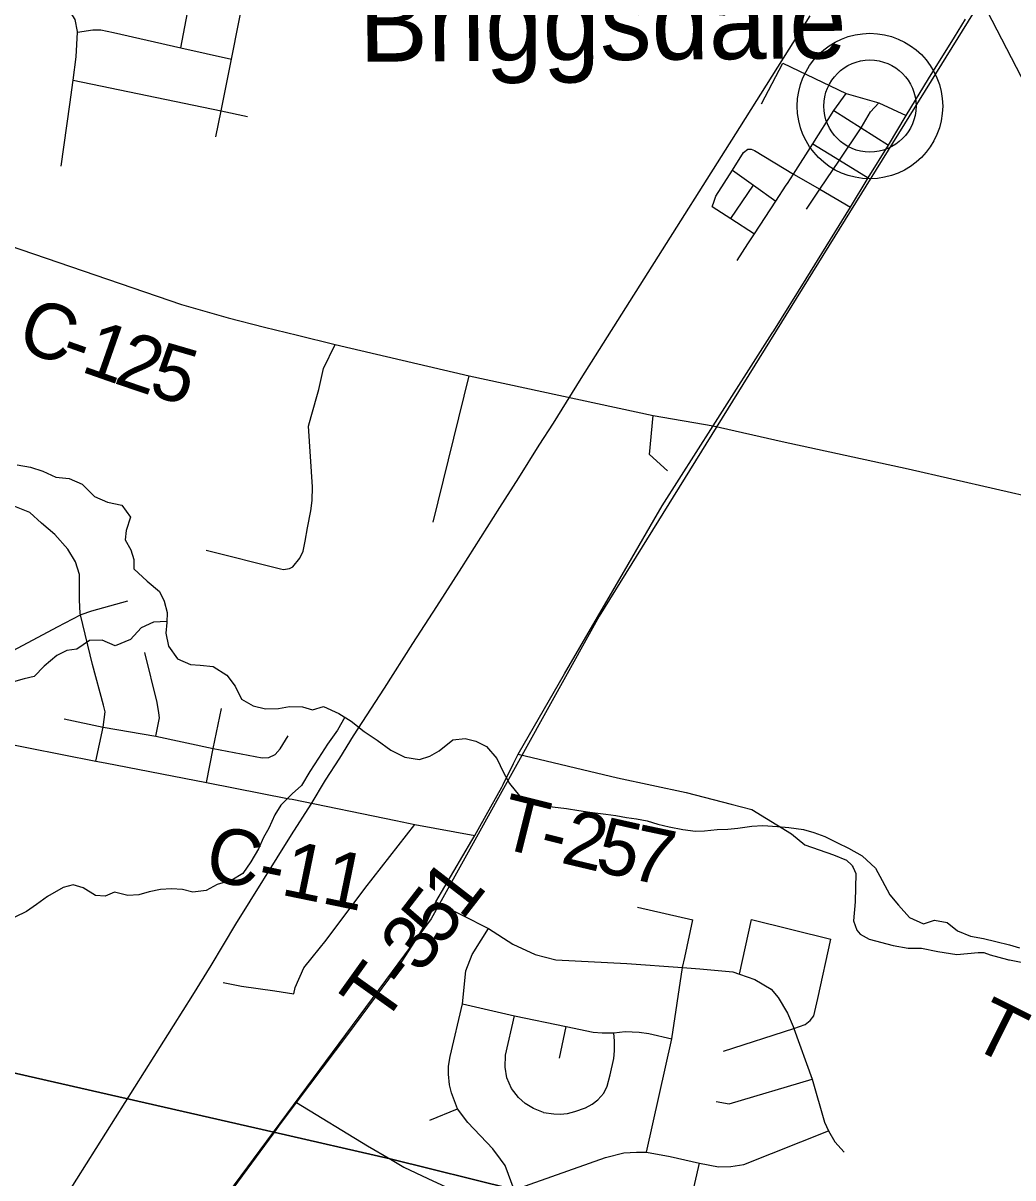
# Model space of a CAD drawing. Extents: x 114604 to 551442, y 316898 to 567001.
# Drawn here: x 185178 to 190526, y 367898 to 374135 of the extents above; entities that cross this region are included whole.
import ezdxf

# ---------------------------------------------------------------- set-up
doc = ezdxf.new("R2010")
doc.units = 0
for name, color, linetype in [('_CIVIL_CONSTRUCTION', 7, 'Continuous'), ('GE_P_Alignment_1000_Bearings', 7, 'Continuous'), ('GE_P_Alignment_1000_Cardinal_Points', 7, 'Continuous'), ('GE_P_Alignment_1000_Stations', 7, 'Continuous'), ('GE_P_Alignment_100_Cardinal_Points', 7, 'Continuous'), ('GE_P_Alignment_500_Bearings', 7, 'Continuous'), ('GE_P_Alignment_500_Distances', 7, 'Continuous'), ('GE_X_Alignment', 7, 'Continuous'), ('PM_P_Cells', 7, 'Continuous'), ('PM_P_CL_Double_Solid', 7, 'Continuous'), ('PM_P_Crosswalk', 7, 'Continuous'), ('PM_X_Dotted_Line', 7, 'Continuous')]:
    doc.layers.add(name, color=color, linetype=linetype)

msp = doc.modelspace()

# ---------------------------------------------------------------- linework, layer by layer
at = {"layer": '_CIVIL_CONSTRUCTION'}
for p, q in [((189949.7, 373634.7), (189975.3, 373676.9)), ((189853.7, 373476.1), (189949.7, 373634.7)), ((189744.8, 373299.6), (189853.7, 373476.1)), ((189648.8, 373141.3), (189744.8, 373299.6)), ((188907.3, 371960.1), (189225.7, 372459.5)), ((187408.5, 369387.9), (187603.1, 369720)), ((187603.1, 369720), (187618.9, 369746.9)), ((187361.9, 369285), (187408.5, 369387.9)), ((186559.8, 368176.3), (186656.3, 368304.9))]:
    msp.add_line(p, q, dxfattribs=at)
for points in [[(189975.3, 373676.9), (190070.1, 373833.1), (190210, 374057.7), (190270.8, 374155.2)], [(189225.7, 372459.5), (189234.4, 372473.1), (189410, 372754), (189648.8, 373141.3)], [(188585.9, 371449.3), (188631.2, 371527.2), (188907.3, 371960.1)], [(187852.5, 370186), (188103.8, 370620.8), (188447.3, 371211.2), (188585.9, 371449.3)], [(187771.5, 370023.3), (187828, 370136.7), (187852.5, 370186)], [(187618.9, 369746.9), (187645.7, 369795.4), (187764.1, 370008.5), (187771.5, 370023.3)], [(187310.8, 369200.2), (187338.6, 369244), (187355.3, 369270.3), (187361.9, 369285)], [(186656.3, 368304.9), (186933.1, 368673.1), (187227.3, 369068.9), (187310.8, 369200.2)], [(186242.3, 367746), (186534.1, 368142), (186559.8, 368176.3)]]:
    msp.add_lwpolyline(points, dxfattribs=at)
at = {"layer": 'GE_P_Alignment_1000_Bearings'}
for points in [[(196041.6, 380963.5), (194033.4, 377563.3), (193868.1, 377325.2), (192058.1, 375431.3), (190340.5, 374234.8), (188290.1, 370932.4), (187383.2, 369296.1), (186211.4, 367713.7), (185191.3, 366327.4), (183802.2, 363991.4), (182496.1, 361739.6), (179755.4, 357652.8), (178697.7, 356015.2), (176027.5, 351942.2), (171808.5, 345313.1), (170010.5, 342458.8), (166009.2, 336033.6), (165560.1, 335287.7), (165457.7, 335042), (165304.5, 334515.6), (164243.2, 330883.3)], [(185312.5, 367643.3), (186094.8, 368883.9), (186194, 369044.8), (186328, 369267.7), (186628.1, 369750.6), (186734.2, 369916.1), (186812.3, 370045), (186889, 370165.2), (186963.5, 370284.4), (187130.1, 370542.6), (187284.5, 370784.3), (187414.5, 370983.4), (187549.5, 371194.4), (187754, 371517.7), (187856.9, 371679.1), (187967.1, 371854.2), (188043.7, 371974.1), (188066.7, 372012.4), (188194.5, 372215.9), (188534.9, 372753.5), (189050.5, 373571.6), (189430.4, 374173.3)]]:
    msp.add_lwpolyline(points, dxfattribs=at)
at = {"layer": 'GE_P_Alignment_1000_Cardinal_Points'}
for p, q in [((189168.7, 373699.2), (189283.1, 373917.9)), ((185384.2, 373361.5), (185430.4, 373694.6)), ((189001.6, 373078.8), (189124.6, 373259.5)), ((187393.8, 371440), (187588.4, 372230.1))]:
    msp.add_line(p, q, dxfattribs=at)
for points in [[(189283.1, 373917.9), (189625.8, 373755.2), (189802.5, 373703.1), (189949.7, 373634.7)], [(189307.9, 373268.7), (189340.3, 373319.4), (189444.9, 373483.1), (189559.3, 373662), (189625.8, 373755.2)], [(189411, 373129.1), (189483.3, 373236.8), (189589.4, 373394.7), (189706.3, 373569.2), (189757.3, 373656.1), (189802.5, 373703.1)], [(189559.3, 373662), (189706.3, 373569.2), (189853.7, 373476.1)], [(189444.9, 373483.1), (189589.4, 373394.7), (189744.8, 373299.6)], [(188901.9, 373143.4), (188907.9, 373161.4), (188921.9, 373199.6), (189010.6, 373341), (189070.4, 373436.4), (189094.5, 373454.4)], [(189094.5, 373454.4), (189112.5, 373454.4), (189130.5, 373446.4), (189340.3, 373319.4), (189483.3, 373236.8), (189648.8, 373141.3)], [(189010.6, 373341), (189124.6, 373259.5), (189245.5, 373173)], [(189098.2, 372947.4), (189129.8, 372995.8), (189245.5, 373173), (189301.4, 373258.6), (189307.9, 373268.7)], [(188901.9, 373143.4), (189001.6, 373078.8), (189129.8, 372995.8)], [(189036, 372852.3), (189095, 372942.6), (189098.2, 372947.4)], [(188660.7, 371716.5), (188562.5, 371804.8), (188583, 372014.9)], [(187852.5, 370186), (188390, 370059.1), (188760.4, 369979.6), (189004.2, 369916.5), (189114.9, 369888), (189329.7, 369756.6), (189401.4, 369697.3), (189557.7, 369643), (189627.9, 369612.9), (189655.9, 369586.8), (189658.1, 369582.4), (189662.5, 369573.5)], [(186258.4, 368953.7), (186358.2, 368933.7), (186538.8, 368907.5), (186640.3, 368891.1), (186648.6, 368925.5), (186695.5, 369031.5), (186740.2, 369087.7), (186815.2, 369181.1), (187024.5, 369461.1), (187294.3, 369806.2)], [(189662.5, 369573.5), (189678, 369542.6), (189673.9, 369388.1), (189665.8, 369285.8), (189683.8, 369235.6), (189701.8, 369213.5), (189750, 369187.4), (189880.2, 369153.2), (189960.4, 369139.1), (190032.6, 369139.1), (190120.8, 369121), (190223, 369104.9), (190339.2, 369114.9), (190369.3, 369114.9), (190403.4, 369102.8), (190449.5, 369090.8), (190497.6, 369076.7), (190502.8, 369075.7), (190508.1, 369074.7)], [(190508.1, 369074.7), (190571.7, 369062.6), (190619.8, 369056.6), (190647.9, 369042.5), (190708, 369012.4), (190826.2, 368922), (190870.3, 368908), (190922.4, 368893.9), (191042.7, 368903.9), (191168.9, 368911.9), (191237.1, 368897.8), (191359.3, 368845.6), (191477.6, 368789.3), (191533.7, 368773.2), (191593.8, 368769.2), (191792.3, 368801.3)]]:
    msp.add_lwpolyline(points, dxfattribs=at)
at = {"layer": 'GE_P_Alignment_1000_Stations'}
for p, q in [((189949.7, 373634.7), (189975.3, 373676.9)), ((189853.7, 373476.1), (189949.7, 373634.7)), ((189744.8, 373299.6), (189853.7, 373476.1)), ((189648.8, 373141.3), (189744.8, 373299.6)), ((188907.3, 371960.1), (189225.7, 372459.5)), ((187408.5, 369387.9), (187603.1, 369720)), ((187603.1, 369720), (187618.9, 369746.9)), ((187361.9, 369285), (187408.5, 369387.9)), ((186559.8, 368176.3), (186656.3, 368304.9))]:
    msp.add_line(p, q, dxfattribs=at)
for points in [[(189975.3, 373676.9), (190070.1, 373833.1), (190210, 374057.7), (190270.8, 374155.2)], [(189225.7, 372459.5), (189234.4, 372473.1), (189410, 372754), (189648.8, 373141.3)], [(188585.9, 371449.3), (188631.2, 371527.2), (188907.3, 371960.1)], [(187852.5, 370186), (188103.8, 370620.8), (188447.3, 371211.2), (188585.9, 371449.3)], [(187771.5, 370023.3), (187828, 370136.7), (187852.5, 370186)], [(187618.9, 369746.9), (187645.7, 369795.4), (187764.1, 370008.5), (187771.5, 370023.3)], [(187310.8, 369200.2), (187338.6, 369244), (187355.3, 369270.3), (187361.9, 369285)], [(186656.3, 368304.9), (186933.1, 368673.1), (187227.3, 369068.9), (187310.8, 369200.2)], [(186242.3, 367746), (186534.1, 368142), (186559.8, 368176.3)]]:
    msp.add_lwpolyline(points, dxfattribs=at)
at = {"layer": 'GE_P_Alignment_100_Cardinal_Points'}
for p, q in [((188498.8, 369359.9), (188797.3, 369291.6)), ((188075.9, 368543.6), (188112.4, 368714.6)), ((188963.2, 368581.4), (189342.8, 368704.4)), ((187376.2, 368208.9), (187525.1, 368271.5))]:
    msp.add_line(p, q, dxfattribs=at)
for points in [[(186219.7, 373519.8), (186247.9, 373660.2), (186303.9, 373939.1), (186382.6, 374331.4), (186385.8, 374391.7), (186382, 374409.8), (186372.9, 374453.7), (186298.3, 374621.4), (186296, 374628.6), (186268.9, 374711.4), (186266.2, 374761.6), (186271.3, 374829.9), (186283.9, 374890.5), (186299.4, 374964.9), (186339.9, 375145), (186444.4, 375610.1), (186627.6, 376425.5), (186629.3, 376430.7), (186677.6, 376576.8), (186702.1, 376689.7)], [(185430.4, 373694.6), (185448.3, 373826.5), (185465.5, 373953.2), (185471.4, 374085.6), (185471.6, 374089.8), (185458.7, 374153.9), (185425.8, 374207.7), (185389.2, 374245.3), (185302.3, 374292.3), (185225.4, 374335.4), (185206.9, 374371.3), (185191.5, 374427.7), (185189.9, 374433.3), (185198.9, 374511.8), (185267.8, 374785.3), (185299.5, 374910.8), (185330.8, 374963.5), (185376.8, 375027.3), (185427.2, 375097.4), (185437.3, 375114.6), (185487.9, 375200.7), (185530.8, 375321.8), (185668.3, 375914.1), (185828.1, 376620.8)], [(186030.9, 374001.3), (186080.7, 374266.9), (186080.4, 374289), (186074.2, 374305), (186057.9, 374320.8), (185975.4, 374337.8), (185689.8, 374402.1), (185649.5, 374413.6), (185619.2, 374425.2), (185590.8, 374451), (185570.6, 374462.7), (185545.8, 374510.6), (185534.9, 374572.7), (185536.2, 374618.9), (185539.8, 374651.1), (185554.7, 374721)], [(190359.6, 374251.5), (190596.5, 373795.7), (190644.8, 373732.5), (190695.1, 373677.8), (190737.7, 373641.2), (190810.9, 373591.7), (190886.3, 373556.9), (191092.2, 373511)], [(185471.4, 374085.6), (185555.7, 374099), (185597.8, 374097.6), (185666.2, 374084.5), (186030.9, 374001.3), (186303.9, 373939.1)], [(185448.3, 373826.5), (186247.9, 373660.2), (186390.6, 373630.6)], [(186635.8, 371198), (186673.2, 371244.7), (186690.7, 371283.2), (186702, 371337.5), (186715, 371408), (186733.8, 371500.6), (186741, 371556.9), (186742, 371629.3), (186721.2, 371958.3), (186734.5, 372010.7), (186776.6, 372155.9), (186801, 372268.6), (186864.3, 372399.1)], [(185572, 370148.7), (185610.4, 370332.9), (185620.8, 370414.5), (185613.5, 370451.2), (185552.8, 370671.2), (185487.7, 370938.7), (185486.2, 370945.1), (185483.1, 371019.4), (185482.2, 371103.7), (185482.9, 371155.9), (185461.7, 371224.5), (185420.5, 371293.3), (185349.3, 371372.5), (185277.9, 371433.7), (185214.5, 371490.7), (185124.8, 371528.1), (185086.9, 371544.6), (185056.9, 371545)], [(186167.2, 371287.9), (186569.8, 371187.1), (186585.8, 371183.3), (186617.8, 371189.8), (186635.8, 371198)], [(184682.7, 370512.1), (185002.8, 370682.1), (185014.4, 370688.2), (185365, 370874.4), (185487.7, 370938.7), (185492.1, 370941), (185550.5, 370960.3), (185743.7, 371013.9)], [(185895.2, 370282.7), (185916, 370383.3), (185912.3, 370409.5), (185903, 370465.8), (185836.3, 370735.7)], [(186169.3, 370032.7), (186204.8, 370216.9), (186249.9, 370433)], [(185400.3, 370377.2), (185610.4, 370332.9), (185895.2, 370282.7), (186204.8, 370216.9), (186470.5, 370167.1), (186505.3, 370168.4), (186541, 370184.5), (186567.7, 370214.6), (186609.9, 370285.4)], [(187408.5, 369387.9), (187693.4, 369245.1), (187823.7, 369159.7), (187945.7, 369103.8), (188057.5, 369076.2), (188440.5, 369055), (188741.5, 369033.5), (188835.2, 369026.8), (189013.5, 369010.6), (189049.2, 368997.9), (189131.7, 368968.5), (189219.8, 368916.3), (189257.8, 368872.1), (189307.9, 368787.9), (189339.9, 368715.6), (189342.8, 368704.4), (189442.6, 368430.4), (189508.9, 368198), (189529.5, 368152.3), (189563.5, 368092), (189613.8, 368037.1)], [(188546.1, 368036.2), (188682.7, 368648.7), (188741.5, 369033.5), (188753.1, 369087.2), (188797.3, 369291.6)], [(189049.2, 368997.9), (189113.8, 369293.4), (189542.5, 369186.9)], [(187927.2, 367554.7), (187831.3, 367833.2), (187782.7, 367964), (187758.6, 367999.7), (187716.7, 368054.2), (187580.4, 368196.4), (187525.1, 368271.5), (187492.6, 368357), (187482.8, 368400.9), (187476.1, 368458.5), (187476.9, 368501.5), (187485.9, 368554), (187553.1, 368838.4), (187570.9, 369015.2), (187605.1, 369103.5), (187653.2, 369181.7), (187693.4, 369245.1)], [(189342.8, 368704.4), (189404.1, 368725.6), (189430.1, 368747.7), (189450.1, 368773.7), (189472.2, 368866), (189542.5, 369186.9)], [(187553.1, 368838.4), (187834.3, 368773.4), (188112.4, 368714.6), (188259.3, 368684.9), (188307.2, 368680.4), (188370.4, 368681.8), (188430.7, 368688), (188506.3, 368685.7), (188560, 368678.4), (188682.7, 368648.7)], [(187990, 368251.6), (187936.4, 368272.2), (187891.2, 368299.1), (187854.3, 368331.3), (187817.2, 368381.4), (187791.7, 368437.8), (187782.9, 368495.3), (187785.5, 368561.4), (187834.3, 368773.4)], [(187990, 368251.6), (188045.2, 368243), (188080.7, 368242.3), (188118.9, 368246.4), (188159, 368256.2), (188217.3, 368276.8), (188253.5, 368295.2), (188283, 368319.3), (188315.3, 368356), (188334.2, 368392.5), (188350, 368453.9), (188369.5, 368543), (188374, 368583.2), (188374.6, 368636.9), (188370.4, 368681.8)], [(188922.5, 368310.9), (188992.6, 368297.9), (189442.6, 368430.4)], [(186656.3, 368304.9), (187039.7, 368071.2), (187163.3, 367998.6), (187235.3, 367956.3), (187365.6, 367894.3), (187512.5, 367825.3), (187536.4, 367815.9), (187577, 367804.3), (187616.1, 367797.4), (187671.7, 367793.9), (187717.8, 367798.9), (187831.3, 367833.2), (188325.5, 368007.6), (188423.6, 368032.6), (188492.3, 368037.1), (188546.1, 368036.2), (188674.2, 368012.9), (188833.3, 367977.7), (188935.8, 367958.2), (189003.1, 367958.7), (189071.7, 367969.9), (189529.5, 368152.3)], [(188681, 366765.2), (188609.1, 366856.7), (188593.8, 366897.8), (188596.3, 366935.4), (188605.4, 366977.6), (188754, 367636.3), (188768, 367694.5), (188833.3, 367977.7)]]:
    msp.add_lwpolyline(points, dxfattribs=at)
at = {"layer": 'GE_P_Alignment_500_Bearings'}
for p, q in [((186660.8, 372448.8), (186864.3, 372399.1)), ((186631.6, 369942.4), (187192.4, 369827.2))]:
    msp.add_line(p, q, dxfattribs=at)
for points in [[(184798.1, 373038.7), (185103.7, 372932.9), (186033.6, 372613.9), (186286.1, 372542.5), (186482.8, 372492.3), (186660.8, 372448.8)], [(186864.3, 372399.1), (187588.4, 372230.1), (188583, 372014.9), (188907.3, 371960.1)], [(188907.3, 371960.1), (189279.1, 371875.4), (189960.9, 371726.7), (190668.1, 371566.1), (190751.3, 371547), (190848.5, 371525.3), (190955.3, 371491.3), (191031.6, 371462.2), (191138.4, 371413.2), (191237.1, 371361), (191392.4, 371276.5), (191470.8, 371236.3), (191567.4, 371197.6), (191639, 371174.6), (191726.8, 371150.2), (191813.6, 371135.9), (191943.7, 371126.2), (192039.1, 371120.8), (192266.3, 371100.6), (192451.1, 371077.3), (192555.7, 371062.8), (192637.6, 371047.8), (192979.8, 370982.8)], [(184732.4, 370315.3), (184822.3, 370296.4), (185033.4, 370255.2), (185207.6, 370219.7), (185572, 370148.7), (185621.8, 370139)], [(185621.8, 370139), (186169.3, 370032.7), (186616.3, 369945.5), (186631.6, 369942.4)], [(187192.4, 369827.2), (187294.3, 369806.2), (187618.9, 369746.9)]]:
    msp.add_lwpolyline(points, dxfattribs=at)
at = {"layer": 'GE_P_Alignment_500_Distances'}
for points in [[(205863.2, 363742), (199063.9, 365202.5), (198263.5, 365328.3), (198158.4, 365346.5), (195803.7, 365900.1), (193600.8, 366427), (192977.8, 366676.8), (191394.8, 367037.4), (189047.6, 367572), (188752.8, 367639.1), (188453.2, 367707.4), (188394.5, 367720.8), (187830.1, 367836), (187162.2, 368001.5), (186532.9, 368144.8), (182913.3, 368969.2), (177781.1, 370138.2)], [(177781.1, 370138.2), (182913.3, 368969.2), (186532.9, 368144.8), (187162.2, 368001.5), (187830.1, 367836), (188394.5, 367720.8), (188453.2, 367707.4), (188752.8, 367639.1), (189047.6, 367572), (191394.8, 367037.4), (192977.8, 366676.8), (193600.8, 366427), (195803.7, 365900.1), (198158.4, 365346.5), (198263.5, 365328.3), (199063.9, 365202.5), (205863.2, 363742)]]:
    msp.add_lwpolyline(points, dxfattribs=at)
at = {"layer": 'GE_X_Alignment'}
for radius in [392.9, 249]:
    msp.add_circle((189754, 373686.6), radius, dxfattribs=at)
at = {"layer": 'PM_P_Cells'}
for points in [[(185145.4, 371748.5), (185217.4, 371736), (185285.3, 371715.5), (185355.1, 371683), (185427.1, 371674.5), (185496.9, 371644), (185564.5, 371577.4), (185634.4, 371546.9), (185712.3, 371530.4), (185757.9, 371465.9), (185735.4, 371393.9), (185729.1, 371343.8), (185760.8, 371289.5), (185776.5, 371237.3), (185776.2, 371187.1), (185847.8, 371120.5), (185915.4, 371064), (185941.1, 371011.7), (185956.7, 370951.4), (185954.4, 370897.3), (185950, 370839.2), (185963.6, 370769), (186013.1, 370700.5), (186083, 370670), (186135, 370667.6), (186205, 370659.2), (186278.7, 370612.6), (186324.4, 370554.2), (186357.9, 370483.8), (186421.7, 370447.3), (186487.6, 370430.8), (186557.7, 370432.4), (186617.8, 370444), (186687.8, 370441.6), (186741.7, 370425.2), (186801.9, 370442.9), (186883.7, 370406.3), (186951.5, 370363.7), (187021.1, 370309.2), (187090.9, 370262.6), (187164.6, 370208), (187240.3, 370169.4), (187320.3, 370156.9), (187376.5, 370174.6), (187426.7, 370204.3), (187501.1, 370264)], [(185954.7, 370903.6), (185882.4, 370899.8), (185816.1, 370868.1), (185757.7, 370806.4), (185675.4, 370770.8), (185605.6, 370801.3), (185537.5, 370799.7), (185469.2, 370754.1), (185415.1, 370746.4), (185360.9, 370718.7), (185292.5, 370661), (185238.1, 370605.2), (185184, 370593.5), (185125.9, 370577.8)], [(186916.5, 370385.7), (186877.1, 370316.1), (186822.6, 370240.3), (186774.1, 370164.4), (186727.6, 370092.5), (186683.1, 370016.6), (186632.8, 369972.8), (186570.4, 369911.1), (186538, 369859.2), (186505.5, 369787.2), (186477.2, 369735.3), (186450.8, 369675.3), (186408.3, 369605.4), (186365.9, 369541.5), (186305.6, 369505.8), (186227.4, 369482.3), (186167.2, 369450.6), (186095.1, 369441), (186039.2, 369455.4), (185979.2, 369459.8), (185921.1, 369456.2), (185859, 369442.5), (185802.9, 369426.9), (185744.8, 369423.2), (185672.9, 369441.7), (185620.8, 369420), (185568.7, 369422.3), (185503, 369464.8), (185449, 369481.2), (185394.9, 369465.5), (185310.6, 369418), (185250.3, 369374.2), (185196, 369336.5), (185133.8, 369306.8)], [(187501.1, 370264), (187567.2, 370271.6), (187625.1, 370257.2), (187682.9, 370226.8), (187738.5, 370162.3), (187774.1, 370087.8), (187805.7, 370027.5), (187861.3, 369961), (187917.2, 369932.6), (187969.1, 369916.2), (188039, 369901.7), (188115, 369893.2), (188181, 369882.8), (188240.9, 369872.4), (188326.9, 369861.8), (188380.9, 369855.4), (188438.9, 369845), (188492.8, 369836.7), (188550.8, 369826.3), (188608.7, 369807.9), (188668.6, 369793.4), (188742.6, 369778.9), (188810.6, 369770.5), (188860.6, 369772.2), (188928.7, 369779.7), (188986.7, 369781.4), (189040.8, 369787), (189114.9, 369796.6), (189174.9, 369800.2), (189254.9, 369795.7), (189314.9, 369789.3), (189394.9, 369778.8), (189450.8, 369762.4), (189510.7, 369741.9), (189578.5, 369707.4), (189638.4, 369679), (189712.1, 369636.4), (189783.7, 369569.8), (189819.3, 369503.4), (189860.9, 369426.9), (189908.5, 369370.5), (189968.1, 369304), (190043.9, 369269.4), (190102.1, 369289.1), (190172.1, 369276.6), (190227.8, 369232.1), (190297.7, 369203.6), (190367.6, 369191.1), (190433.5, 369174.7), (190507.4, 369156.2), (190561.4, 369139.8)]]:
    msp.add_lwpolyline(points, dxfattribs=at)
at = {"layer": 'PM_X_Dotted_Line'}
msp.add_line((189754, 373686.6), (189754, 373686.6), dxfattribs=at)

# ---------------------------------------------------------------- texts
at = {"layer": '_CIVIL_CONSTRUCTION'}
msp.add_text('Briggsdale', height=417.03, rotation=0.41304, dxfattribs=at).set_placement((186994.4, 373925.4))
at = {"layer": 'PM_P_CL_Double_Solid'}
for s, height, rotation, p in [('C', 300, 340.43755, (185133.3, 372379.4)), ('1', 300, 340.68232, (185482.9, 372255.3)), ('-', 300, 340.48154, (185365.8, 372296.8)), ('2', 300, 341.326, (185660.8, 372192.9)), ('5', 300, 343.71558, (185849, 372129.6)), ('C-11', 300.02, 348.39356, (186149.4, 369513.8))]:
    msp.add_text(s, height=height, rotation=rotation, dxfattribs=at).set_placement(p)
at = {"layer": 'PM_P_Crosswalk'}
for s, rotation, p in [('T', 345.95065, (187735.3, 369686.4)), ('2', 346.60619, (188076.2, 369601.5)), ('5', 347.32804, (188260, 369557.8)), ('7', 348.16927, (188445, 369516.2)), ('-', 346.1157, (187953.9, 369631.7)), ('1', 52.2254, (187550.6, 369284.6)), ('5', 52.25141, (187437.5, 369138.5)), ('3', 52.32945, (187324.6, 368992.3)), ('T', 54.47229, (187121.1, 368714.2)), ('-', 52.6017, (187250, 368894.8)), ('T', 333.56057, (190282.4, 368613.6))]:
    msp.add_text(s, height=300, rotation=rotation, dxfattribs=at).set_placement(p)

doc.saveas('drawing.dxf')
